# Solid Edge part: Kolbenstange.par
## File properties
Author: bmolnar
Last saved by: bmolnar
Revision: 77
Sűrűség: 0,000 kg/m^3
Pontosság: 0,990
Username: bmolnar
Dokumentum tartalom típus: 0
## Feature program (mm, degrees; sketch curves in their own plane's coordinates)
base feature "unnamed BaseFeature 1"
sketch for "unnamed Protrusion 1" plane through (18.4, 0, 0) normal (1, 0, 0) x-axis (0, 1, 0)
  circle centre (0, 0) radius 8
extrude "unnamed Protrusion 1" add finite 19.7 along +normal
sketch for "Kihúzás_2" #1 plane through (18.4, 0, 0) normal (1, 0, 0) x-axis (0, 1, 0)
  circle centre (0, 0) radius 4
sketch for "Kihúzás_2" #2 plane through (18.4, 0, 0) normal (1, 0, 0) x-axis (0, 1, 0)
  circle centre (0, 0) radius 8
extrude "Kihúzás_2" add finite 5.5 along -normal
sketch for "Furat_1" plane through (2, 0, 0.0012) normal (-1, 0, 0) x-axis (0, 0, 1)
  hole centre (-0.0012, 0) bore radius 1.621
hole "Furat_1" nominal diameter 4 finite  VBottomAngle = 118 deg; ThreadDepth = 9 mm
chamfer "Letörés_1" setback 0.2  SetBackValue2 = 45 deg
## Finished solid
Body 1: solid body, 18 faces, 24 edges, 13 vertices.
  Faces by surface: plane 8, cylinder 5, cone 3, torus 2
  Edges by curve: circle 14, line 6, curve on surface 2, ellipse 2
Bounding box of the edges (mm; curved faces can reach further): 38.100 x 16.000 x 16.000, from (0, -8, -8) to (38.1, 8, 8).
Cylindrical faces by radius (mm): R1.621 x2, R2.125 x1, R4 x1, R8 x1
Conical faces (half-angle, radius in mm at the cone's reference point): 45 deg R1.821 x1, 45 deg R2.225 x1, 59 deg R1.621 x1
Toroidal faces (ring radius, tube radius in mm): R1.925 r0.2 x1, R2.7 r1.3 x1
Planar faces by outward normal: +x 1, +z 1, -x 3, -z 1, oblique 2
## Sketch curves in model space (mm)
circle centre (18.4, 0, 0) radius 8
circle centre (18.4, 0, 0) radius 4
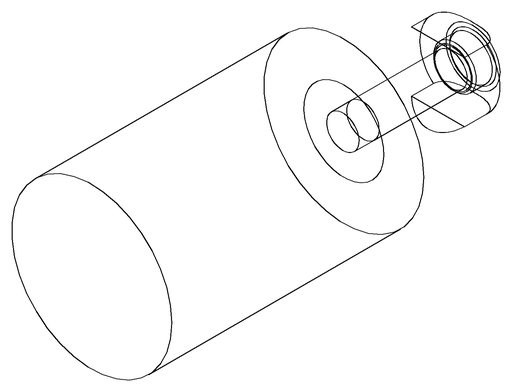
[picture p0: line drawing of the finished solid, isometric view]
